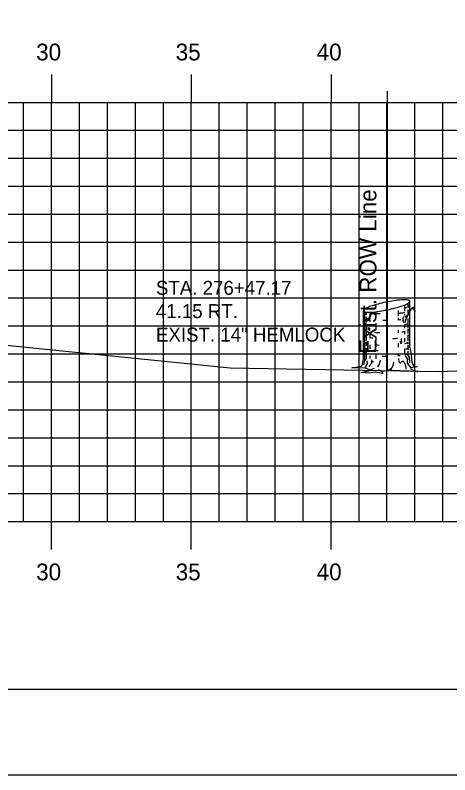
# Model space of a CAD drawing. Extents: x 854008 to 854178, y 366268 to 366378.
# Drawn here: x 854119.8 to 854135.35, y 366268.18 to 366295.35 of the extents above; entities that cross this region are included whole.
import ezdxf

# ---------------------------------------------------------------- set-up
doc = ezdxf.new("R2010")
doc.units = 0
for name, color, linetype in [('BORDER', 7, 'Continuous'), ('D_Text_Monospaced', 7, 'Continuous'), ('E_ROW_Line', 7, 'Continuous'), ('H_V ANNOTATION', 7, 'Continuous'), ('MAJOR', 7, 'Continuous'), ('MINOR', 7, 'Continuous'), ('PLOT BOUNDARY', 7, 'Continuous'), ('S_Roadway_Centerline', 7, 'Continuous'), ('S_Trees_Conifer_Pay', 7, 'Continuous')]:
    doc.layers.add(name, color=color, linetype=linetype)

msp = doc.modelspace()

# ---------------------------------------------------------------- linework, layer by layer
at = {"layer": 'BORDER'}
msp.add_line((854016.103, 366271.236), (854176.103, 366271.236), dxfattribs=at)
at = {"layer": 'E_ROW_Line'}
msp.add_line((854133.124, 366282.64), (854133.124, 366292.64), dxfattribs=at)
at = {"layer": 'MAJOR'}
for p, q in [((854121.103, 366293.238), (854121.103, 366292.236)), ((854126.103, 366293.238), (854126.103, 366292.236)), ((854131.103, 366293.238), (854131.103, 366292.236)), ((854021.103, 366292.236), (854161.103, 366292.236)), ((854021.103, 366292.236), (854161.103, 366292.236)), ((854121.103, 366277.236), (854121.103, 366292.236)), ((854126.103, 366277.236), (854126.103, 366292.236)), ((854131.103, 366277.236), (854131.103, 366292.236)), ((854021.103, 366287.236), (854161.103, 366287.236)), ((854021.103, 366282.236), (854161.103, 366282.236)), ((854021.103, 366277.236), (854161.103, 366277.236)), ((854021.103, 366277.236), (854161.103, 366277.236)), ((854121.103, 366276.234), (854121.103, 366277.236)), ((854126.103, 366276.234), (854126.103, 366277.236)), ((854131.103, 366276.234), (854131.103, 366277.236))]:
    msp.add_line(p, q, dxfattribs=at)
at = {"layer": 'MINOR'}
for p, q in [((854120.103, 366277.236), (854120.103, 366292.236)), ((854122.103, 366277.236), (854122.103, 366292.236)), ((854123.103, 366277.236), (854123.103, 366292.236)), ((854124.103, 366277.236), (854124.103, 366292.236)), ((854125.103, 366277.236), (854125.103, 366292.236)), ((854127.103, 366277.236), (854127.103, 366292.236)), ((854128.103, 366277.236), (854128.103, 366292.236)), ((854129.103, 366277.236), (854129.103, 366292.236)), ((854130.103, 366277.236), (854130.103, 366292.236)), ((854132.103, 366277.236), (854132.103, 366292.236)), ((854133.103, 366277.236), (854133.103, 366292.236)), ((854134.103, 366277.236), (854134.103, 366292.236)), ((854135.103, 366277.236), (854135.103, 366292.236)), ((854021.103, 366291.236), (854161.103, 366291.236)), ((854021.103, 366290.236), (854161.103, 366290.236)), ((854021.103, 366289.236), (854161.103, 366289.236)), ((854021.103, 366288.236), (854161.103, 366288.236)), ((854021.103, 366286.236), (854161.103, 366286.236)), ((854021.103, 366285.236), (854161.103, 366285.236)), ((854021.103, 366284.236), (854161.103, 366284.236)), ((854021.103, 366283.236), (854161.103, 366283.236)), ((854021.103, 366281.236), (854161.103, 366281.236)), ((854021.103, 366280.236), (854161.103, 366280.236)), ((854021.103, 366279.236), (854161.103, 366279.236)), ((854021.103, 366278.236), (854161.103, 366278.236))]:
    msp.add_line(p, q, dxfattribs=at)
at = {"layer": 'PLOT BOUNDARY'}
msp.add_lwpolyline([(854008.01, 366268.177), (854178.01, 366268.177), (854178.01, 366378.177), (854008.01, 366378.177)], close=True, dxfattribs=at)
at = {"layer": 'S_Roadway_Centerline'}
msp.add_lwpolyline([(854119.24, 366283.569), (854127.488, 366282.734), (854134.932, 366282.61), (854144.452, 366282.95), (854151.493, 366282.391), (854151.803, 366282.4), (854152.599, 366282.401)], dxfattribs=at)
at = {"layer": 'S_Trees_Conifer_Pay'}
for p, q in [((854133.733, 366284.984), (854133.733, 366284.761)), ((854133.85, 366285.045), (854133.85, 366284.882)), ((854133.922, 366283.47), (854133.922, 366285.117)), ((854132.258, 366283.06), (854132.258, 366284.782)), ((854132.305, 366284.744), (854132.305, 366284.273)), ((854132.363, 366284.733), (854132.363, 366284.635)), ((854132.488, 366284.725), (854132.488, 366284.493)), ((854132.708, 366284.746), (854132.708, 366284.578)), ((854133.504, 366284.788), (854133.504, 366284.588)), ((854133.733, 366284.672), (854133.733, 366284.625)), ((854133.85, 366284.815), (854133.85, 366284.687)), ((854132.363, 366284.561), (854132.363, 366284.357)), ((854132.488, 366284.452), (854132.488, 366284.378)), ((854133.114, 366284.514), (854133.114, 366284.419)), ((854133.504, 366284.53), (854133.504, 366284.442)), ((854133.79, 366284.489), (854133.738, 366284.429)), ((854133.85, 366284.5), (854133.85, 366284.164)), ((854132.305, 366284.209), (854132.305, 366283.901)), ((854132.363, 366284.299), (854132.363, 366284.1)), ((854132.708, 366284.341), (854132.708, 366284.104)), ((854133.504, 366284.094), (854133.504, 366283.989)), ((854133.733, 366284.29), (854133.733, 366284.158)), ((854133.85, 366284.127), (854133.85, 366283.964)), ((854132.305, 366283.853), (854132.305, 366283.361)), ((854132.363, 366284.053), (854132.363, 366283.717)), ((854132.488, 366283.975), (854132.488, 366283.836)), ((854132.708, 366283.859), (854132.708, 366283.707)), ((854133.114, 366283.901), (854133.114, 366283.826)), ((854133.733, 366284.047), (854133.733, 366283.937)), ((854133.85, 366283.917), (854133.85, 366283.7)), ((854132.363, 366283.664), (854132.363, 366283.528)), ((854132.488, 366283.565), (854132.488, 366283.423)), ((854132.708, 366283.664), (854132.708, 366283.49)), ((854133.114, 366283.801), (854133.114, 366283.653)), ((854133.504, 366283.622), (854133.504, 366283.476)), ((854133.733, 366283.801), (854133.733, 366283.66)), ((854133.85, 366283.67), (854133.85, 366283.595)), ((854133.85, 366283.555), (854133.85, 366283.381)), ((854132.305, 366283.307), (854132.305, 366283.06)), ((854132.363, 366283.429), (854132.363, 366283.05)), ((854133.114, 366283.361), (854133.114, 366283.208)), ((854133.733, 366283.433), (854133.733, 366283.26)), ((854132.488, 366283.161), (854132.488, 366283.067)), ((854132.708, 366283.213), (854132.708, 366283.06)), ((854133.504, 366283.244), (854133.504, 366283.155)), ((854132.488, 366282.667), (854132.651, 366282.731)), ((854132.925, 366282.603), (854132.8, 366282.667))]:
    msp.add_line(p, q, dxfattribs=at)
for points in [[(854133.738, 366284.615), (854133.775, 366284.541), (854133.822, 366284.598), (854133.88, 366284.666), (854133.973, 366284.86), (854134.037, 366284.907), (854134.068, 366284.914)], [(854133.753, 366284.362), (854133.79, 366284.489), (854133.853, 366284.605), (854133.884, 366284.672), (854133.953, 366284.818)], [(854133.967, 366284.848), (854134.043, 366284.856), (854134.115, 366284.757)], [(854133.705, 366284.578), (854133.674, 366284.493), (854133.67, 366284.425), (854133.701, 366284.362)], [(854132.437, 366284.088), (854132.431, 366284.183), (854132.474, 366284.16), (854132.474, 366284.065)], [(854133.576, 366283.689), (854133.588, 366283.612), (854133.635, 366283.622), (854133.623, 366283.789)], [(854133.922, 366283.47), (854133.973, 366283.208), (854133.989, 366282.935), (854134.047, 366282.809), (854134.183, 366282.778), (854133.952, 366282.741), (854133.952, 366282.741), (854133.958, 366282.694), (854134.206, 366282.599), (854133.931, 366282.616), (854133.576, 366282.636), (854133.254, 366282.626), (854133.261, 366282.708), (854133.113, 366282.626), (854132.925, 366282.603), (854132.95, 366282.535), (854132.682, 366282.578), (854132.462, 366282.551), (854132.169, 366282.568), (854132.458, 366282.626), (854132.488, 366282.667), (854132.326, 366282.725), (854132.089, 366282.735), (854131.848, 366282.735), (854132.19, 366282.793), (854132.231, 366282.873), (854132.258, 366283.06)], [(854133.847, 366283.328), (854133.853, 366283.182), (854133.901, 366283.114), (854133.911, 366282.914)], [(854132.305, 366283.013), (854132.284, 366282.935), (854132.264, 366282.84)], [(854132.546, 366283.019), (854132.546, 366282.887), (854132.458, 366282.788)], [(854132.773, 366282.778), (854132.84, 366282.873), (854132.867, 366283.013)], [(854133.511, 366283.077), (854133.522, 366282.951), (854133.596, 366282.908)], [(854133.748, 366283.182), (854133.822, 366283.077), (854133.827, 366282.904), (854133.952, 366282.741)], [(854132.384, 366282.992), (854132.389, 366282.877), (854132.336, 366282.788), (854132.326, 366282.725)], [(854133.261, 366282.708), (854133.335, 366282.85), (854133.345, 366282.951)], [(854133.79, 366282.688), (854133.775, 366282.826), (854133.701, 366282.955)]]:
    msp.add_lwpolyline(points, dxfattribs=at)
for centre, radius, start, end in [((854134.113, 366280.014), 5.179, 95.3794, 101.7194), ((854133.703, 366284.372), 0.802, 79.2194, 95.3794), ((854132.756, 366284.176), 0.802, 108.0594, 124.2194), ((854134.113, 366280.014), 5.179, 101.7194, 108.0594), ((854132.066, 366289.884), 5.179, 281.7194, 288.0594), ((854133.423, 366285.723), 0.802, 288.0594, 304.2194), ((854133.591, 366285.431), 0.571, 284.4317, 292.4132), ((854133.806, 366284.913), 0.251, 71.0501, 79.2194), ((854133.733, 366285.267), 0.251, 304.2194, 312.3887), ((854133.79, 366285.086), 0.172, 300, 311.2506), ((854133.861, 366285.073), 0.0817, 56.7194, 71.0501), ((854133.847, 366285.143), 0.0817, 312.3887, 326.7194), ((854133.862, 366285.003), 0.0624, 311.2506, 330), ((854133.877, 366285.097), 0.0527, 46.923, 56.7194), ((854133.891, 366285.113), 0.0314, 34.2194, 46.923), ((854133.871, 366285.127), 0.0527, 326.7194, 336.5158), ((854133.878, 366284.994), 0.0441, 330, 343.9485), ((854133.896, 366285.116), 0.0264, 23.4074, 34.2194), ((854133.89, 366285.118), 0.0314, 336.5158, 349.2194), ((854133.899, 366285.117), 0.0226, 11.7194, 23.4074), ((854133.899, 366285.117), 0.0226, 0.0315, 11.7194), ((854133.895, 366285.117), 0.0264, 349.2194, 0.0315), ((854133.888, 366284.991), 0.0334, 343.9485, 354.2151), ((854132.289, 366284.781), 0.0314, 156.5158, 169.2194), ((854132.284, 366284.781), 0.0264, 169.2194, 180.0315), ((854132.28, 366284.781), 0.0226, 180.0315, 191.7194), ((854132.28, 366284.781), 0.0226, 191.7194, 203.4074), ((854132.284, 366284.783), 0.0264, 203.4074, 214.2194), ((854132.309, 366284.772), 0.0527, 146.7194, 156.5158), ((854132.288, 366284.786), 0.0314, 214.2194, 226.923), ((854132.333, 366284.756), 0.0817, 132.3887, 146.7194), ((854132.302, 366284.801), 0.0527, 226.923, 236.7194), ((854132.318, 366284.826), 0.0817, 236.7194, 251.0501), ((854132.447, 366284.631), 0.251, 124.2194, 132.3887), ((854132.373, 366284.985), 0.251, 251.0501, 259.2194), ((854132.476, 366285.527), 0.802, 259.2194, 275.3794), ((854132.066, 366289.884), 5.179, 275.3794, 281.7194), ((854133.09, 366288.794), 4.124, 264.6955, 266.7331), ((854133.09, 366288.794), 4.124, 276.238, 278.1032), ((854133.591, 366285.276), 0.571, 278.1032, 284.3667), ((854133.591, 366285.276), 0.571, 297.0237, 300), ((854133.79, 366284.931), 0.172, 300, 311.2506), ((854133.862, 366284.848), 0.0624, 311.2506, 330), ((854133.878, 366284.839), 0.0441, 330, 343.9485), ((854133.888, 366284.836), 0.0334, 343.9485, 354.2151), ((854132.29, 366284.603), 0.0334, 163.9485, 180), ((854132.29, 366284.603), 0.0334, 180, 196.0515), ((854132.3, 366284.606), 0.0441, 196.0515, 210), ((854132.316, 366284.616), 0.0624, 210, 228.7494), ((854132.388, 366284.698), 0.172, 228.7494, 240), ((854132.588, 366285.043), 0.571, 240, 240.3367), ((854132.588, 366285.043), 0.571, 246.8597, 257.9846), ((854133.088, 366288.561), 4.124, 268.0751, 270), ((854133.088, 366288.561), 4.124, 270, 270.3581), ((854133.088, 366288.561), 4.124, 275.7849, 277.0558), ((854133.888, 366284.392), 0.0334, 343.9485, 354.2151), ((854132.29, 366284.157), 0.0334, 163.9485, 180), ((854132.29, 366284.157), 0.0334, 180, 196.0515), ((854132.3, 366284.16), 0.0441, 196.0515, 210), ((854132.316, 366284.169), 0.0624, 210, 228.7494), ((854132.388, 366284.251), 0.172, 228.7494, 240), ((854132.588, 366284.596), 0.571, 240, 240.3367), ((854132.589, 366284.832), 0.571, 240, 247.0587), ((854133.09, 366288.35), 4.124, 273.7052, 275.9504), ((854133.59, 366284.832), 0.571, 284.4493, 297.0429), ((854133.589, 366284.596), 0.571, 297.1896, 300), ((854133.788, 366284.251), 0.172, 300, 311.2506), ((854133.861, 366284.169), 0.0624, 311.2506, 330), ((854133.877, 366284.16), 0.0441, 330, 343.9485), ((854133.887, 366284.157), 0.0334, 343.9485, 354.2151), ((854132.29, 366283.947), 0.0334, 163.9485, 180), ((854132.29, 366283.947), 0.0334, 180, 196.0515), ((854132.3, 366283.95), 0.0441, 196.0515, 210), ((854132.316, 366283.959), 0.0624, 210, 228.7494), ((854132.388, 366284.041), 0.172, 228.7494, 240), ((854132.588, 366284.386), 0.571, 240, 246.8597), ((854132.588, 366284.386), 0.571, 259.2707, 261.8968), ((854133.088, 366287.904), 4.124, 261.8968, 263.1474), ((854133.088, 366288.114), 4.124, 264.081, 266.6676), ((854133.088, 366288.114), 4.124, 277.6125, 278.1032), ((854133.589, 366284.596), 0.571, 278.1032, 286.9296), ((854133.589, 366284.386), 0.571, 297.1896, 300), ((854133.788, 366284.041), 0.172, 300, 311.2506), ((854133.861, 366283.959), 0.0624, 311.2506, 330), ((854133.877, 366283.95), 0.0441, 330, 343.9485), ((854133.887, 366283.947), 0.0334, 343.9485, 354.2151), ((854132.29, 366283.71), 0.0334, 163.9485, 180), ((854132.29, 366283.71), 0.0334, 180, 196.0515), ((854132.3, 366283.713), 0.0441, 196.0515, 210), ((854132.316, 366283.722), 0.0624, 210, 228.7494), ((854132.388, 366283.805), 0.172, 228.7494, 240), ((854132.588, 366284.15), 0.571, 240, 246.8597), ((854133.088, 366287.667), 4.124, 264.716, 266.3193), ((854133.088, 366287.904), 4.124, 270, 270.3581), ((854133.088, 366287.904), 4.124, 273.1493, 275.4569), ((854133.589, 366284.15), 0.571, 285.3983, 297.1896), ((854132.29, 366283.512), 0.0334, 163.9485, 180), ((854132.29, 366283.317), 0.0334, 163.9485, 180), ((854132.29, 366283.317), 0.0334, 180, 196.0515), ((854132.3, 366283.32), 0.0441, 196.0515, 210), ((854132.316, 366283.329), 0.0624, 210, 228.7494), ((854132.388, 366283.411), 0.172, 228.7494, 240), ((854132.577, 366283.958), 0.571, 241.2369, 248.0268), ((854133.088, 366287.47), 4.124, 263.4991, 265.8397), ((854133.589, 366283.952), 0.571, 289.2907, 300), ((854133.788, 366283.607), 0.172, 300, 311.2506), ((854133.861, 366283.524), 0.0624, 311.2506, 330), ((854133.877, 366283.515), 0.0441, 330, 343.9485), ((854133.887, 366283.512), 0.0334, 343.9485, 354.2151), ((854132.29, 366283.096), 0.0334, 163.9485, 180), ((854132.29, 366283.096), 0.0334, 180, 196.0515), ((854132.3, 366283.099), 0.0441, 196.0515, 210), ((854132.316, 366283.108), 0.0624, 210, 228.7494), ((854132.388, 366283.191), 0.172, 228.7494, 240), ((854132.588, 366283.756), 0.571, 240, 246.8597), ((854132.588, 366283.536), 0.571, 240, 244.5314), ((854133.088, 366287.274), 4.124, 267.8117, 270), ((854133.088, 366287.274), 4.124, 270, 270.1328), ((854133.088, 366287.274), 4.124, 275.7849, 276.7896), ((854133.589, 366283.756), 0.571, 288.5067, 297.2721), ((854133.788, 366283.191), 0.172, 300, 311.2506), ((854133.861, 366283.108), 0.0624, 311.2506, 330), ((854133.877, 366283.099), 0.0441, 330, 343.9485), ((854133.887, 366283.096), 0.0334, 343.9485, 354.2151), ((854133.088, 366287.054), 4.124, 262.4438, 263.512), ((854133.088, 366287.054), 4.124, 277.3684, 278.1032), ((854133.589, 366283.536), 0.571, 278.1032, 281.637)]:
    msp.add_arc(centre, radius, start, end, dxfattribs=at)

# ---------------------------------------------------------------- texts
at = {"layer": 'D_Text_Monospaced'}
for s, height, p in [('STA. 276+47.17', 0.49998, (854124.836, 366285.35)), ('41.15 RT.', 0.5, (854124.836, 366284.516)), ('EXIST. 14" HEMLOCK', 0.49998, (854124.836, 366283.676))]:
    msp.add_text(s, height=height, dxfattribs=at).set_placement(p)
at = {"layer": 'E_ROW_Line'}
msp.add_text('Exist. ROW Line', height=0.6, rotation=90, dxfattribs=at).set_placement((854132.724, 366283.24))
at = {"layer": 'H_V ANNOTATION'}
for s, p in [('30', (854120.552, 366293.736)), ('35', (854125.544, 366293.736)), ('40', (854130.589, 366293.736)), ('30', (854120.552, 366275.136)), ('35', (854125.544, 366275.136)), ('40', (854130.589, 366275.136))]:
    msp.add_text(s, height=0.6, dxfattribs=at).set_placement(p)

doc.saveas('drawing.dxf')
